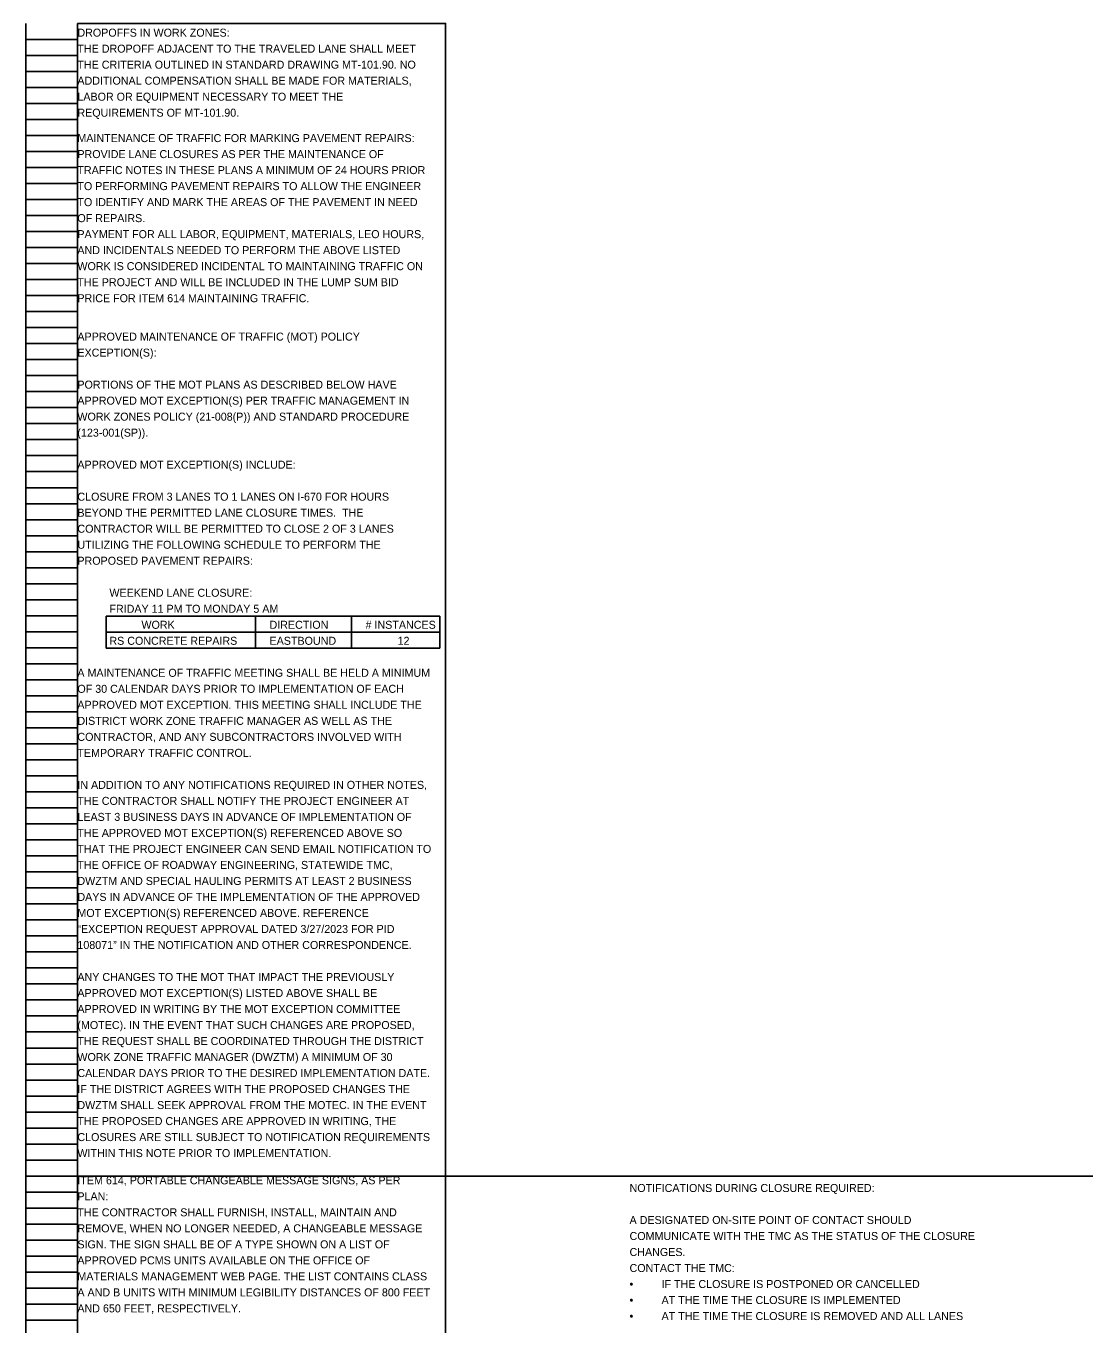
# Model space of a CAD drawing. Extents: x 16463 to 16500, y 5400 to 5823.
# Drawn here: x 16463.05 to 16481.55, y 5740.24 to 5762.95 of the extents above; entities that cross this region are included whole.
import ezdxf

# ---------------------------------------------------------------- set-up
doc = ezdxf.new("R2010")
doc.units = 0
for name, color, linetype in [('Default', 7, 'Continuous'), ('SC_Scratch1', 7, 'Continuous'), ('SH_Data', 7, 'Continuous')]:
    doc.layers.add(name, color=color, linetype=linetype)

msp = doc.modelspace()

# ---------------------------------------------------------------- linework, layer by layer
at = {"layer": 'Default'}
for p, q in [((16464.453, 5752.624), (16470.289, 5752.624)), ((16464.453, 5752.624), (16464.453, 5752.064)), ((16467.062, 5752.624), (16467.062, 5752.064)), ((16468.743, 5752.624), (16468.743, 5752.064)), ((16470.289, 5752.624), (16470.289, 5752.064)), ((16464.453, 5752.344), (16470.289, 5752.344)), ((16464.453, 5752.064), (16470.289, 5752.064))]:
    msp.add_line(p, q, dxfattribs=at)
at = {"layer": 'SC_Scratch1'}
msp.add_line((16470.389, 5742.832), (16500.06, 5742.832), dxfattribs=at)
for points in [[(16463.949, 5762.992), (16470.389, 5762.992), (16470.389, 5742.832), (16463.949, 5742.832)], [(16463.949, 5742.832), (16470.389, 5742.832), (16470.389, 5722.672), (16463.949, 5722.672)]]:
    msp.add_lwpolyline(points, close=True, dxfattribs=at)
at = {"layer": 'SH_Data'}
for p, q in [((16463.049, 5742.832), (16463.049, 5762.992)), ((16463.949, 5742.832), (16463.949, 5762.992)), ((16463.049, 5762.712), (16463.949, 5762.712)), ((16463.049, 5762.432), (16463.949, 5762.432)), ((16463.049, 5762.152), (16463.949, 5762.152)), ((16463.049, 5761.872), (16463.949, 5761.872)), ((16463.049, 5761.592), (16463.949, 5761.592)), ((16463.049, 5761.312), (16463.949, 5761.312)), ((16463.049, 5761.032), (16463.949, 5761.032)), ((16463.049, 5760.752), (16463.949, 5760.752)), ((16463.049, 5760.472), (16463.949, 5760.472)), ((16463.049, 5760.192), (16463.949, 5760.192)), ((16463.049, 5759.912), (16463.949, 5759.912)), ((16463.049, 5759.632), (16463.949, 5759.632)), ((16463.049, 5759.352), (16463.949, 5759.352)), ((16463.049, 5759.072), (16463.949, 5759.072)), ((16463.049, 5758.792), (16463.949, 5758.792)), ((16463.049, 5758.512), (16463.949, 5758.512)), ((16463.049, 5758.232), (16463.949, 5758.232)), ((16463.049, 5757.952), (16463.949, 5757.952)), ((16463.049, 5757.672), (16463.949, 5757.672)), ((16463.049, 5757.392), (16463.949, 5757.392)), ((16463.049, 5757.112), (16463.949, 5757.112)), ((16463.049, 5756.832), (16463.949, 5756.832)), ((16463.049, 5756.552), (16463.949, 5756.552)), ((16463.049, 5756.272), (16463.949, 5756.272)), ((16463.049, 5755.992), (16463.949, 5755.992)), ((16463.049, 5755.712), (16463.949, 5755.712)), ((16463.049, 5755.432), (16463.949, 5755.432)), ((16463.049, 5755.152), (16463.949, 5755.152)), ((16463.049, 5754.872), (16463.949, 5754.872)), ((16463.049, 5754.592), (16463.949, 5754.592)), ((16463.049, 5754.312), (16463.949, 5754.312)), ((16463.049, 5754.032), (16463.949, 5754.032)), ((16463.049, 5753.752), (16463.949, 5753.752)), ((16463.049, 5753.472), (16463.949, 5753.472)), ((16463.049, 5753.192), (16463.949, 5753.192)), ((16463.049, 5752.912), (16463.949, 5752.912)), ((16463.049, 5752.632), (16463.949, 5752.632)), ((16463.049, 5752.352), (16463.949, 5752.352)), ((16463.049, 5752.072), (16463.949, 5752.072)), ((16463.049, 5751.792), (16463.949, 5751.792)), ((16463.049, 5751.512), (16463.949, 5751.512)), ((16463.049, 5751.232), (16463.949, 5751.232)), ((16463.049, 5750.952), (16463.949, 5750.952)), ((16463.049, 5750.672), (16463.949, 5750.672)), ((16463.049, 5750.392), (16463.949, 5750.392)), ((16463.049, 5750.112), (16463.949, 5750.112)), ((16463.049, 5749.832), (16463.949, 5749.832)), ((16463.049, 5749.552), (16463.949, 5749.552)), ((16463.049, 5749.272), (16463.949, 5749.272)), ((16463.049, 5748.992), (16463.949, 5748.992)), ((16463.049, 5748.712), (16463.949, 5748.712)), ((16463.049, 5748.432), (16463.949, 5748.432)), ((16463.049, 5748.152), (16463.949, 5748.152)), ((16463.049, 5747.872), (16463.949, 5747.872)), ((16463.049, 5747.592), (16463.949, 5747.592)), ((16463.049, 5747.312), (16463.949, 5747.312)), ((16463.049, 5747.032), (16463.949, 5747.032)), ((16463.049, 5746.752), (16463.949, 5746.752)), ((16463.049, 5746.472), (16463.949, 5746.472)), ((16463.049, 5746.192), (16463.949, 5746.192)), ((16463.049, 5745.912), (16463.949, 5745.912)), ((16463.049, 5745.632), (16463.949, 5745.632)), ((16463.049, 5745.352), (16463.949, 5745.352)), ((16463.049, 5745.072), (16463.949, 5745.072)), ((16463.049, 5744.792), (16463.949, 5744.792)), ((16463.049, 5744.512), (16463.949, 5744.512)), ((16463.049, 5744.232), (16463.949, 5744.232)), ((16463.049, 5743.952), (16463.949, 5743.952)), ((16463.049, 5743.672), (16463.949, 5743.672)), ((16463.049, 5743.392), (16463.949, 5743.392)), ((16463.049, 5743.112), (16463.949, 5743.112)), ((16463.049, 5722.672), (16463.049, 5742.832)), ((16463.049, 5742.832), (16463.949, 5742.832)), ((16463.049, 5742.832), (16463.949, 5742.832)), ((16463.949, 5722.672), (16463.949, 5742.832)), ((16463.049, 5742.552), (16463.949, 5742.552)), ((16463.049, 5742.272), (16463.949, 5742.272)), ((16463.049, 5741.992), (16463.949, 5741.992)), ((16463.049, 5741.712), (16463.949, 5741.712)), ((16463.049, 5741.432), (16463.949, 5741.432)), ((16463.049, 5741.152), (16463.949, 5741.152)), ((16463.049, 5740.872), (16463.949, 5740.872)), ((16463.049, 5740.592), (16463.949, 5740.592)), ((16463.049, 5740.312), (16463.949, 5740.312))]:
    msp.add_line(p, q, dxfattribs=at)

# ---------------------------------------------------------------- texts
at = {"layer": 'Default'}
for s, p in [('DROPOFFS IN WORK ZONES:', (16463.949, 5762.76)), ('THE DROPOFF ADJACENT TO THE TRAVELED LANE SHALL MEET ', (16463.949, 5762.48)), ('THE CRITERIA OUTLINED IN STANDARD DRAWING MT-101.90. NO ', (16463.949, 5762.2)), ('ADDITIONAL COMPENSATION SHALL BE MADE FOR MATERIALS, ', (16463.949, 5761.92)), ('LABOR OR EQUIPMENT NECESSARY TO MEET THE ', (16463.949, 5761.64)), ('REQUIREMENTS OF MT-101.90.', (16463.949, 5761.36)), ('MAINTENANCE OF TRAFFIC FOR MARKING PAVEMENT REPAIRS:', (16463.949, 5760.916)), ('PROVIDE LANE CLOSURES AS PER THE MAINTENANCE OF ', (16463.949, 5760.636)), ('TRAFFIC NOTES IN THESE PLANS A MINIMUM OF 24 HOURS PRIOR ', (16463.949, 5760.356)), ('TO PERFORMING PAVEMENT REPAIRS TO ALLOW THE ENGINEER ', (16463.949, 5760.076)), ('TO IDENTIFY AND MARK THE AREAS OF THE PAVEMENT IN NEED ', (16463.949, 5759.796)), ('OF REPAIRS.', (16463.949, 5759.516)), ('PAYMENT FOR ALL LABOR, EQUIPMENT, MATERIALS, LEO HOURS, ', (16463.949, 5759.236)), ('AND INCIDENTALS NEEDED TO PERFORM THE ABOVE LISTED ', (16463.949, 5758.956)), ('WORK IS CONSIDERED INCIDENTAL TO MAINTAINING TRAFFIC ON ', (16463.949, 5758.676)), ('THE PROJECT AND WILL BE INCLUDED IN THE LUMP SUM BID ', (16463.949, 5758.396)), ('PRICE FOR ITEM 614 MAINTAINING TRAFFIC.', (16463.949, 5758.116)), ('APPROVED MAINTENANCE OF TRAFFIC (MOT) POLICY ', (16463.949, 5757.444)), ('EXCEPTION(S):', (16463.949, 5757.164)), ('PORTIONS OF THE MOT PLANS AS DESCRIBED BELOW HAVE ', (16463.949, 5756.604)), ('APPROVED MOT EXCEPTION(S) PER TRAFFIC MANAGEMENT IN ', (16463.949, 5756.324)), ('WORK ZONES POLICY (21-008(P)) AND STANDARD PROCEDURE ', (16463.949, 5756.044)), ('(123-001(SP)). ', (16463.949, 5755.764)), ('APPROVED MOT EXCEPTION(S) INCLUDE: ', (16463.949, 5755.204)), ('CLOSURE FROM 3 LANES TO 1 LANES ON I-670 FOR HOURS ', (16463.949, 5754.644)), ('BEYOND THE PERMITTED LANE CLOSURE TIMES.  THE ', (16463.949, 5754.364)), ('CONTRACTOR WILL BE PERMITTED TO CLOSE 2 OF 3 LANES ', (16463.949, 5754.084)), ('UTILIZING THE FOLLOWING SCHEDULE TO PERFORM THE ', (16463.949, 5753.804)), ('PROPOSED PAVEMENT REPAIRS:', (16463.949, 5753.524)), ('WEEKEND LANE CLOSURE:', (16464.509, 5752.964)), ('FRIDAY 11 PM TO MONDAY 5 AM', (16464.509, 5752.684)), ('WORK', (16465.069, 5752.404)), ('DIRECTION', (16467.309, 5752.404)), ('# INSTANCES', (16468.989, 5752.404)), ('RS CONCRETE REPAIRS', (16464.509, 5752.124)), ('EASTBOUND', (16467.309, 5752.124)), ('12', (16469.549, 5752.124)), ('A MAINTENANCE OF TRAFFIC MEETING SHALL BE HELD A MINIMUM ', (16463.949, 5751.564)), ('OF 30 CALENDAR DAYS PRIOR TO IMPLEMENTATION OF EACH ', (16463.949, 5751.284)), ('APPROVED MOT EXCEPTION. THIS MEETING SHALL INCLUDE THE ', (16463.949, 5751.004)), ('DISTRICT WORK ZONE TRAFFIC MANAGER AS WELL AS THE ', (16463.949, 5750.724)), ('CONTRACTOR, AND ANY SUBCONTRACTORS INVOLVED WITH ', (16463.949, 5750.444)), ('TEMPORARY TRAFFIC CONTROL. ', (16463.949, 5750.164)), ('IN ADDITION TO ANY NOTIFICATIONS REQUIRED IN OTHER NOTES, ', (16463.949, 5749.604)), ('THE CONTRACTOR SHALL NOTIFY THE PROJECT ENGINEER AT ', (16463.949, 5749.324)), ('LEAST 3 BUSINESS DAYS IN ADVANCE OF IMPLEMENTATION OF ', (16463.949, 5749.044)), ('THE APPROVED MOT EXCEPTION(S) REFERENCED ABOVE SO ', (16463.949, 5748.764)), ('THAT THE PROJECT ENGINEER CAN SEND EMAIL NOTIFICATION TO ', (16463.949, 5748.484)), ('THE OFFICE OF ROADWAY ENGINEERING, STATEWIDE TMC, ', (16463.949, 5748.204)), ('DWZTM AND SPECIAL HAULING PERMITS AT LEAST 2 BUSINESS ', (16463.949, 5747.924)), ('DAYS IN ADVANCE OF THE IMPLEMENTATION OF THE APPROVED ', (16463.949, 5747.644)), ('MOT EXCEPTION(S) REFERENCED ABOVE. REFERENCE ', (16463.949, 5747.364)), ('“EXCEPTION REQUEST APPROVAL DATED 3/27/2023 FOR PID ', (16463.949, 5747.084)), ('108071” IN THE NOTIFICATION AND OTHER CORRESPONDENCE. ', (16463.949, 5746.804)), ('ANY CHANGES TO THE MOT THAT IMPACT THE PREVIOUSLY ', (16463.949, 5746.244)), ('APPROVED MOT EXCEPTION(S) LISTED ABOVE SHALL BE ', (16463.949, 5745.964)), ('APPROVED IN WRITING BY THE MOT EXCEPTION COMMITTEE ', (16463.949, 5745.684)), ('(MOTEC). IN THE EVENT THAT SUCH CHANGES ARE PROPOSED, ', (16463.949, 5745.404)), ('THE REQUEST SHALL BE COORDINATED THROUGH THE DISTRICT ', (16463.949, 5745.124)), ('WORK ZONE TRAFFIC MANAGER (DWZTM) A MINIMUM OF 30 ', (16463.949, 5744.844)), ('CALENDAR DAYS PRIOR TO THE DESIRED IMPLEMENTATION DATE. ', (16463.949, 5744.564)), ('IF THE DISTRICT AGREES WITH THE PROPOSED CHANGES THE ', (16463.949, 5744.284)), ('DWZTM SHALL SEEK APPROVAL FROM THE MOTEC. IN THE EVENT ', (16463.949, 5744.004)), ('THE PROPOSED CHANGES ARE APPROVED IN WRITING, THE ', (16463.949, 5743.724)), ('CLOSURES ARE STILL SUBJECT TO NOTIFICATION REQUIREMENTS ', (16463.949, 5743.444)), ('WITHIN THIS NOTE PRIOR TO IMPLEMENTATION. ', (16463.949, 5743.164)), ('ITEM 614, PORTABLE CHANGEABLE MESSAGE SIGNS, AS PER ', (16463.949, 5742.688)), ('NOTIFICATIONS DURING CLOSURE REQUIRED:', (16473.606, 5742.554)), ('PLAN:', (16463.949, 5742.408)), ('THE CONTRACTOR SHALL FURNISH, INSTALL, MAINTAIN AND ', (16463.949, 5742.128)), ('REMOVE, WHEN NO LONGER NEEDED, A CHANGEABLE MESSAGE ', (16463.949, 5741.848)), ('A DESIGNATED ON-SITE POINT OF CONTACT SHOULD ', (16473.606, 5741.994)), ('COMMUNICATE WITH THE TMC AS THE STATUS OF THE CLOSURE ', (16473.606, 5741.714)), ('SIGN. THE SIGN SHALL BE OF A TYPE SHOWN ON A LIST OF ', (16463.949, 5741.568)), ('CHANGES.  ', (16473.606, 5741.434)), ('APPROVED PCMS UNITS AVAILABLE ON THE OFFICE OF ', (16463.949, 5741.288)), ('CONTACT THE TMC: ', (16473.606, 5741.154)), ('MATERIALS MANAGEMENT WEB PAGE. THE LIST CONTAINS CLASS ', (16463.949, 5741.008)), ('A AND B UNITS WITH MINIMUM LEGIBILITY DISTANCES OF 800 FEET ', (16463.949, 5740.728)), ('•', (16473.606, 5740.874)), ('IF THE CLOSURE IS POSTPONED OR CANCELLED', (16474.166, 5740.874)), ('•', (16473.606, 5740.594)), ('AT THE TIME THE CLOSURE IS IMPLEMENTED ', (16474.166, 5740.594)), ('AND 650 FEET, RESPECTIVELY. ', (16463.949, 5740.448)), ('•', (16473.606, 5740.314)), ('AT THE TIME THE CLOSURE IS REMOVED AND ALL LANES ', (16474.166, 5740.314))]:
    msp.add_text(s, height=0.14, dxfattribs=at).set_placement(p)

doc.saveas('drawing.dxf')
